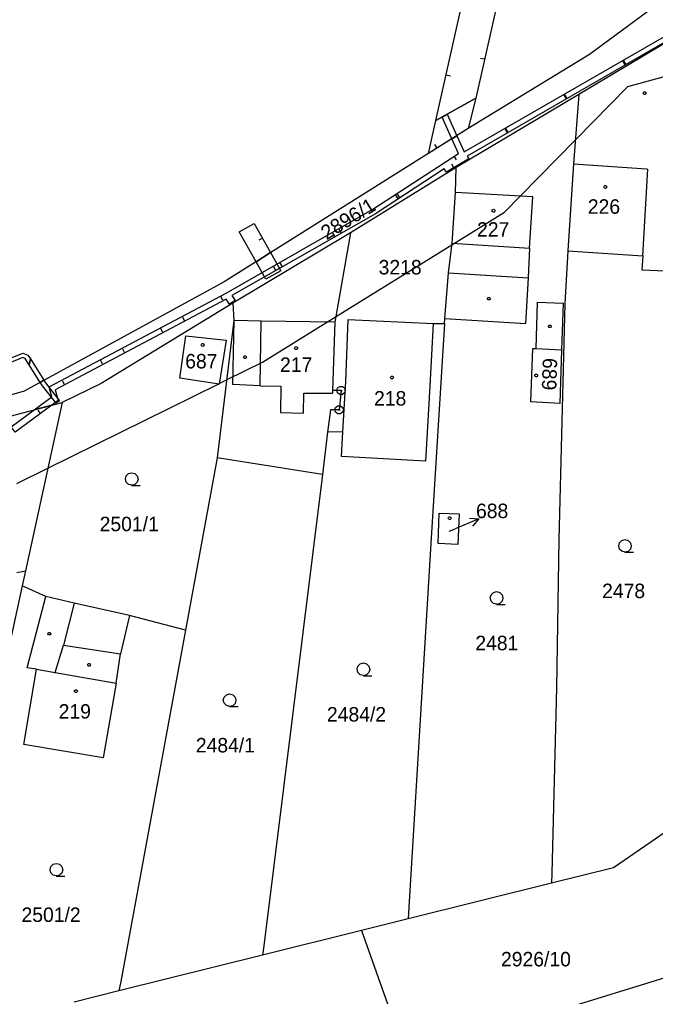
# Model space of a CAD drawing. Extents: x -760611 to -758411, y -1176479 to -1174807.
# Drawn here: x -759231.6 to -759156.8, y -1175131 to -1175016.2 of the extents above; entities that cross this region are included whole.
import ezdxf

# ---------------------------------------------------------------- set-up
doc = ezdxf.new("R2010")
doc.units = 0
for name, color, linetype in [('1', 7, 'Continuous'), ('11', 7, 'Continuous'), ('12', 7, 'Continuous'), ('13', 7, 'Continuous'), ('2', 7, 'Continuous'), ('3', 7, 'Continuous'), ('4', 7, 'Continuous'), ('5', 7, 'Continuous'), ('7', 7, 'Continuous'), ('8', 7, 'Continuous')]:
    doc.layers.add(name, color=color, linetype=linetype)

msp = doc.modelspace()

# ---------------------------------------------------------------- linework, layer by layer
at = {"layer": '1'}
for p, q in [((-759150.3, -1175009.76), (-759164.6, -1175020.29)), ((-759153.04, -1175017.37), (-759165.84, -1175024.98)), ((-759164.6, -1175020.29), (-759178.88, -1175029.01)), ((-759165.84, -1175024.98), (-759180.26, -1175033.56)), ((-759165.84, -1175024.98), (-759166.46, -1175033.14)), ((-759178.88, -1175029.01), (-759207.54, -1175047)), ((-759180.26, -1175033.56), (-759192.72, -1175041.24)), ((-759180.34, -1175036.5), (-759180.26, -1175033.56)), ((-759166.46, -1175033.14), (-759167.14, -1175043.36)), ((-759180.75, -1175042.45), (-759180.34, -1175036.5)), ((-759171.27, -1175037.03), (-759180.34, -1175036.5)), ((-759171.64, -1175043.06), (-759171.27, -1175037.03)), ((-759192.72, -1175041.24), (-759206.53, -1175049.53)), ((-759192.72, -1175041.24), (-759194.56, -1175051.73)), ((-759181.19, -1175045.94), (-759180.75, -1175042.45)), ((-759171.64, -1175043.06), (-759171.82, -1175046.55)), ((-759167.14, -1175043.36), (-759167.51, -1175049.56)), ((-759167.14, -1175043.36), (-759158.34, -1175043.97)), ((-759158.34, -1175043.97), (-759158.43, -1175045.59)), ((-759181.59, -1175051.31), (-759181.19, -1175045.94)), ((-759158.43, -1175045.59), (-759155.64, -1175045.71)), ((-759207.54, -1175047), (-759231.08, -1175059.85)), ((-759171.82, -1175046.55), (-759172.14, -1175051.92)), ((-759206.53, -1175049.53), (-759222.03, -1175058.94)), ((-759206.53, -1175049.53), (-759206.43, -1175051.56)), ((-759170.88, -1175054.86), (-759170.7, -1175049.4)), ((-759170.7, -1175049.4), (-759167.7, -1175049.53)), ((-759167.51, -1175049.56), (-759168.22, -1175077.29)), ((-759167.7, -1175049.53), (-759167.88, -1175055.01)), ((-759206.43, -1175051.56), (-759208.4, -1175067.69)), ((-759194.56, -1175051.73), (-759194.81, -1175059.76)), ((-759193.25, -1175058.7), (-759192.99, -1175051.42)), ((-759192.99, -1175051.42), (-759182.96, -1175051.89)), ((-759182.96, -1175051.89), (-759183.37, -1175059.25)), ((-759181.63, -1175051.91), (-759183.24, -1175077.74)), ((-759182.96, -1175051.89), (-759181.63, -1175051.91)), ((-759181.63, -1175051.91), (-759181.59, -1175051.31)), ((-759181.59, -1175051.31), (-759172.14, -1175051.92)), ((-759212.79, -1175058.33), (-759212.05, -1175053.35)), ((-759212.05, -1175053.35), (-759207.34, -1175053.87)), ((-759207.34, -1175053.87), (-759208.15, -1175059.04)), ((-759171.51, -1175061.09), (-759171.25, -1175054.84)), ((-759171.25, -1175054.84), (-759170.88, -1175054.86)), ((-759167.88, -1175055.01), (-759168.08, -1175061.3)), ((-759222.03, -1175058.94), (-759226.61, -1175061.18)), ((-759208.15, -1175059.04), (-759212.79, -1175058.33)), ((-759193.59, -1175064.62), (-759193.25, -1175058.7)), ((-759231.08, -1175059.85), (-759242.58, -1175063.11)), ((-759193.81, -1175059.77), (-759194.81, -1175059.76)), ((-759193.81, -1175059.77), (-759194.04, -1175062.06)), ((-759183.37, -1175059.25), (-759183.87, -1175068.09)), ((-759259.32, -1175069.76), (-759226.61, -1175061.18)), ((-759226.61, -1175061.18), (-759230.92, -1175080.96)), ((-759168.08, -1175061.3), (-759171.51, -1175061.09)), ((-759195.04, -1175062.03), (-759195.39, -1175064.66)), ((-759194.04, -1175062.06), (-759195.04, -1175062.03)), ((-759195.39, -1175064.66), (-759196.01, -1175069.63)), ((-759193.59, -1175064.62), (-759195.39, -1175064.66)), ((-759193.75, -1175067.53), (-759193.59, -1175064.62)), ((-759208.4, -1175067.69), (-759212.12, -1175087.92)), ((-759196.01, -1175069.63), (-759208.4, -1175067.69)), ((-759183.87, -1175068.09), (-759193.75, -1175067.53)), ((-759196.01, -1175069.63), (-759202.91, -1175125.02)), ((-759182.41, -1175077.77), (-759182.26, -1175074.18)), ((-759182.26, -1175074.18), (-759179.92, -1175074.28)), ((-759179.92, -1175074.28), (-759180.08, -1175077.88)), ((-759168.22, -1175077.29), (-759168.47, -1175094.73)), ((-759183.24, -1175077.74), (-759185.84, -1175120.5)), ((-759180.08, -1175077.88), (-759182.41, -1175077.77)), ((-759231.94, -1175081.17), (-759230.92, -1175080.96)), ((-759230.92, -1175080.96), (-759231.31, -1175082.74)), ((-759231.31, -1175082.74), (-759244.42, -1175142.81)), ((-759228.54, -1175083.99), (-759231.31, -1175082.74)), ((-759230.73, -1175092.35), (-759228.54, -1175083.99)), ((-759225.18, -1175084.75), (-759228.54, -1175083.99)), ((-759218.69, -1175086.22), (-759225.18, -1175084.75)), ((-759218.69, -1175086.22), (-759219.74, -1175090.73)), ((-759212.12, -1175087.92), (-759218.69, -1175086.22)), ((-759212.12, -1175087.92), (-759219.73, -1175129.23)), ((-759220.24, -1175094.16), (-759219.74, -1175090.73)), ((-759231.11, -1175101.38), (-759229.64, -1175092.53)), ((-759229.64, -1175092.53), (-759230.73, -1175092.35)), ((-759220.24, -1175094.16), (-759221.77, -1175102.93)), ((-759168.47, -1175094.73), (-759169.03, -1175116.5)), ((-759221.77, -1175102.93), (-759231.11, -1175101.38)), ((-759154.5, -1175110.85), (-759161.77, -1175115.86)), ((-759161.77, -1175115.86), (-759169.06, -1175117.68)), ((-759169.03, -1175116.5), (-759169.06, -1175117.68)), ((-759169.06, -1175117.68), (-759185.93, -1175121.87)), ((-759185.84, -1175120.5), (-759185.93, -1175121.87)), ((-759185.93, -1175121.87), (-759191.41, -1175123.23)), ((-759191.41, -1175123.23), (-759203.05, -1175126.12)), ((-759191.41, -1175123.23), (-759185.78, -1175139)), ((-759202.91, -1175125.02), (-759203.05, -1175126.12)), ((-759203.05, -1175126.12), (-759219.93, -1175130.32)), ((-759149.08, -1175126.73), (-759169.45, -1175133.02)), ((-759219.73, -1175129.23), (-759219.93, -1175130.32)), ((-759219.93, -1175130.32), (-759225.2, -1175131.63))]:
    msp.add_line(p, q, dxfattribs=at)
at = {"layer": '11'}
for points in [[(-758949.2, -1174976.06), (-758977.51, -1174978.74), (-758983.13, -1174979.27), (-758986.95, -1174979.9), (-758999.15, -1174981.9), (-759005.62, -1174982.97), (-759027.3, -1174991.01), (-759057.42, -1175002.17), (-759065.49, -1175005.94), (-759070.45, -1175006.82), (-759079.49, -1175008.41), (-759092.2, -1175010.11), (-759110.03, -1175012.49), (-759116.16, -1175014.27), (-759121.49, -1175015.82), (-759122.18, -1175015.72), (-759124.46, -1175015.38), (-759134.22, -1175017.02), (-759144.38, -1175019.8), (-759148.15, -1175020.83), (-759150.25, -1175021.4), (-759160.11, -1175024.09)], [(-759231.94, -1175070.7), (-759228.29, -1175068.9), (-759208.26, -1175059.02), (-759208.14, -1175058.96), (-759207.28, -1175058.54), (-759203.05, -1175056.46), (-759194.46, -1175051.13), (-759180.78, -1175042.66), (-759174.58, -1175038.82), (-759172.73, -1175036.94), (-759166.25, -1175030.34), (-759160.11, -1175024.09)]]:
    msp.add_lwpolyline(points, dxfattribs=at)
at = {"layer": '12'}
for p, q in [((-759166.46, -1175033.14), (-759167.14, -1175043.36)), ((-759166.46, -1175033.14), (-759157.9, -1175033.74)), ((-759158.34, -1175043.97), (-759157.74, -1175033.75)), ((-759157.9, -1175033.74), (-759157.74, -1175033.75)), ((-759180.75, -1175042.45), (-759180.34, -1175036.5)), ((-759171.27, -1175037.03), (-759180.34, -1175036.5)), ((-759171.64, -1175043.06), (-759171.27, -1175037.03)), ((-759180.75, -1175042.45), (-759171.64, -1175043.06)), ((-759167.14, -1175043.36), (-759158.34, -1175043.97)), ((-759203.32, -1175059.23), (-759203.22, -1175051.61)), ((-759194.56, -1175051.73), (-759203.22, -1175051.61)), ((-759194.56, -1175051.73), (-759194.81, -1175059.76)), ((-759193.25, -1175058.7), (-759192.99, -1175051.42)), ((-759192.99, -1175051.42), (-759182.96, -1175051.89)), ((-759182.96, -1175051.89), (-759183.37, -1175059.25)), ((-759212.79, -1175058.33), (-759212.05, -1175053.35)), ((-759212.05, -1175053.35), (-759207.34, -1175053.87)), ((-759207.34, -1175053.87), (-759208.15, -1175059.04)), ((-759171.51, -1175061.09), (-759171.25, -1175054.84)), ((-759171.25, -1175054.84), (-759170.88, -1175054.86)), ((-759170.88, -1175054.86), (-759167.88, -1175055.01)), ((-759167.88, -1175055.01), (-759168.08, -1175061.3)), ((-759208.15, -1175059.04), (-759212.79, -1175058.33)), ((-759193.59, -1175064.62), (-759193.25, -1175058.7)), ((-759203.32, -1175059.23), (-759200.9, -1175059.26)), ((-759200.9, -1175059.26), (-759200.95, -1175062.38)), ((-759198.22, -1175062.42), (-759198.19, -1175060.09)), ((-759198.19, -1175060.09), (-759194.82, -1175060.1)), ((-759194.81, -1175059.76), (-759194.82, -1175060.1)), ((-759183.37, -1175059.25), (-759183.87, -1175068.09)), ((-759168.08, -1175061.3), (-759171.51, -1175061.09)), ((-759200.95, -1175062.38), (-759198.22, -1175062.42)), ((-759193.75, -1175067.53), (-759193.59, -1175064.62)), ((-759183.87, -1175068.09), (-759193.75, -1175067.53)), ((-759182.41, -1175077.77), (-759182.26, -1175074.18)), ((-759182.26, -1175074.18), (-759179.92, -1175074.28)), ((-759179.92, -1175074.28), (-759180.08, -1175077.88)), ((-759180.08, -1175077.88), (-759182.41, -1175077.77)), ((-759231.11, -1175101.38), (-759229.64, -1175092.53)), ((-759229.64, -1175092.53), (-759227.42, -1175092.9)), ((-759227.42, -1175092.9), (-759220.24, -1175094.16)), ((-759220.24, -1175094.16), (-759221.77, -1175102.93)), ((-759221.77, -1175102.93), (-759231.11, -1175101.38))]:
    msp.add_line(p, q, dxfattribs=at)
at = {"layer": '13'}
for p, q in [((-759176.94, -1175020.86), (-759177.43, -1175020.75)), ((-759160.71, -1175021.02), (-759160.46, -1175021.45)), ((-759160.3, -1175021.47), (-759160.55, -1175021.03)), ((-759181.45, -1175022.7), (-759180.96, -1175022.81)), ((-759177.96, -1175025.41), (-759182.65, -1175028.07)), ((-759182.65, -1175028.07), (-759177.96, -1175025.41)), ((-759167.64, -1175025.01), (-759167.39, -1175025.44)), ((-759167.23, -1175025.46), (-759167.48, -1175025.03)), ((-759181.93, -1175027.66), (-759181.33, -1175027.32)), ((-759180.78, -1175030.2), (-759181.93, -1175027.66)), ((-759181.33, -1175027.32), (-759180.2, -1175029.84)), ((-759174.57, -1175029), (-759174.32, -1175029.43)), ((-759174.16, -1175029.45), (-759174.41, -1175029.02)), ((-759180.2, -1175029.84), (-759180.78, -1175030.2)), ((-759182.51, -1175031.29), (-759182.78, -1175030.86)), ((-759180.55, -1175032.26), (-759180.27, -1175032.68)), ((-759180.54, -1175033.61), (-759180.79, -1175033.18)), ((-759187.1, -1175037.26), (-759187.37, -1175036.84)), ((-759187.25, -1175036.63), (-759186.97, -1175037.05)), ((-759194.54, -1175041.73), (-759194.79, -1175041.29)), ((-759194.09, -1175040.77), (-759193.84, -1175041.2)), ((-759203.06, -1175041.87), (-759203.49, -1175042.11)), ((-759203.8, -1175044.65), (-759202.09, -1175043.58)), ((-759202.09, -1175043.58), (-759200.88, -1175045.71)), ((-759202.64, -1175046.7), (-759203.8, -1175044.65)), ((-759201.04, -1175044.74), (-759200.79, -1175045.17)), ((-759200.88, -1175045.71), (-759202.64, -1175046.7)), ((-759201.49, -1175045.69), (-759201.73, -1175045.26)), ((-759207.99, -1175048.68), (-759207.76, -1175049.12)), ((-759212.17, -1175051.63), (-759212.41, -1175051.19)), ((-759215.06, -1175052.43), (-759214.83, -1175052.87)), ((-759219.25, -1175055.37), (-759219.48, -1175054.92)), ((-759230.48, -1175056.77), (-759230.35, -1175056.06)), ((-759230.35, -1175056.06), (-759228.75, -1175058.58)), ((-759222.13, -1175056.17), (-759221.9, -1175056.61)), ((-759229.19, -1175058.82), (-759230.48, -1175056.77)), ((-759229.19, -1175058.82), (-759228.75, -1175058.58)), ((-759228.75, -1175058.58), (-759229.19, -1175058.82)), ((-759228.94, -1175059.21), (-759229.19, -1175058.82)), ((-759228.75, -1175058.58), (-759228.56, -1175058.87)), ((-759228.56, -1175058.87), (-759226.92, -1175060.98)), ((-759226.32, -1175059.1), (-759226.55, -1175058.66)), ((-759227.32, -1175061.28), (-759228.94, -1175059.21)), ((-759226.92, -1175060.98), (-759227.32, -1175061.28)), ((-759229.15, -1175062.48), (-759229.45, -1175062.08))]:
    msp.add_line(p, q, dxfattribs=at)
for points in [[(-759182.65, -1175028.07), (-759174.59, -1174992.11), (-759172.64, -1174983.41)], [(-759168.73, -1174984.27), (-759170.69, -1174992.98), (-759174.4, -1175009.55), (-759177.96, -1175025.41)], [(-759179.34, -1175031.74), (-759155.5, -1175018.02), (-759150.23, -1175014.64), (-759151.48, -1175010.63), (-759150.8, -1175010.13), (-759149.44, -1175014.48), (-759138.98, -1175005.71), (-759124.75, -1174987.85), (-759120.27, -1174989.2)], [(-759155.53, -1175018.72), (-759178.98, -1175032.23), (-759178.78, -1175032.57), (-759181.42, -1175034.14), (-759181.67, -1175033.72), (-759189.76, -1175039)], [(-759177.96, -1175025.41), (-759178.88, -1175029.01), (-759183.52, -1175031.92), (-759182.65, -1175028.07)], [(-759227.82, -1175060.51), (-759228.14, -1175059.35), (-759207.33, -1175048.33), (-759190.08, -1175038.48), (-759180.01, -1175031.91), (-759180.78, -1175030.2), (-759180.2, -1175029.84), (-759179.34, -1175031.74)], [(-759189.76, -1175039), (-759206.64, -1175048.63), (-759206.26, -1175049.22), (-759206.93, -1175049.63), (-759207.31, -1175049.06)], [(-759207.31, -1175049.06), (-759227.43, -1175059.69), (-759227.07, -1175060.95), (-759227.81, -1175061.49), (-759229.9, -1175062.04), (-759227.82, -1175060.51)]]:
    msp.add_lwpolyline(points, dxfattribs=at)
for points in [[(-759203.8, -1175044.65), (-759205.78, -1175041.15), (-759204.02, -1175040.16), (-759202.09, -1175043.58)], [(-759280.32, -1175069.22), (-759280.19, -1175068.65), (-759275.46, -1175067.4), (-759267.57, -1175065.52), (-759257.68, -1175064.32), (-759246.5, -1175060.39), (-759241.38, -1175059.01), (-759235.85, -1175057.24), (-759231.22, -1175055.37), (-759230.63, -1175055.61), (-759230.35, -1175056.06), (-759230.48, -1175056.77), (-759230.97, -1175056.01), (-759231.23, -1175055.9), (-759235.83, -1175057.76), (-759241.1, -1175059.45), (-759246.41, -1175060.91), (-759257.6, -1175064.67), (-759257.79, -1175064.7), (-759260.43, -1175065.05), (-759266.85, -1175065.91), (-759275.26, -1175067.9)], [(-759232.14, -1175064.69), (-759232.61, -1175064.04), (-759229.9, -1175062.04), (-759227.81, -1175061.49)]]:
    msp.add_lwpolyline(points, close=True, dxfattribs=at)
at = {"layer": '3'}
for points in [[(-759218.42, -1175070.91), (-759218.8, -1175070.81), (-759219.07, -1175070.54), (-759219.17, -1175070.17), (-759219.07, -1175069.8), (-759218.8, -1175069.53), (-759218.43, -1175069.43), (-759218.06, -1175069.53), (-759217.79, -1175069.8), (-759217.69, -1175070.18), (-759217.79, -1175070.56), (-759218.06, -1175070.83), (-759218.44, -1175070.93), (-759217.44, -1175070.93)], [(-759160.41, -1175078.77), (-759160.79, -1175078.67), (-759161.06, -1175078.4), (-759161.16, -1175078.03), (-759161.06, -1175077.66), (-759160.79, -1175077.39), (-759160.42, -1175077.29), (-759160.05, -1175077.39), (-759159.78, -1175077.66), (-759159.68, -1175078.04), (-759159.78, -1175078.42), (-759160.05, -1175078.69), (-759160.43, -1175078.79), (-759159.43, -1175078.79)], [(-759175.51, -1175084.89), (-759175.89, -1175084.79), (-759176.16, -1175084.52), (-759176.26, -1175084.15), (-759176.16, -1175083.78), (-759175.89, -1175083.51), (-759175.52, -1175083.41), (-759175.15, -1175083.51), (-759174.88, -1175083.78), (-759174.78, -1175084.16), (-759174.88, -1175084.54), (-759175.15, -1175084.81), (-759175.53, -1175084.91), (-759174.53, -1175084.91)], [(-759191.17, -1175093.27), (-759191.55, -1175093.17), (-759191.82, -1175092.9), (-759191.92, -1175092.53), (-759191.82, -1175092.16), (-759191.55, -1175091.89), (-759191.18, -1175091.79), (-759190.81, -1175091.89), (-759190.54, -1175092.16), (-759190.44, -1175092.54), (-759190.54, -1175092.92), (-759190.81, -1175093.19), (-759191.19, -1175093.29), (-759190.19, -1175093.29)], [(-759206.91, -1175096.9), (-759207.29, -1175096.8), (-759207.56, -1175096.53), (-759207.66, -1175096.16), (-759207.56, -1175095.79), (-759207.29, -1175095.52), (-759206.92, -1175095.42), (-759206.55, -1175095.52), (-759206.28, -1175095.79), (-759206.18, -1175096.17), (-759206.28, -1175096.55), (-759206.55, -1175096.82), (-759206.93, -1175096.92), (-759205.93, -1175096.92)], [(-759227.28, -1175116.82), (-759227.66, -1175116.72), (-759227.93, -1175116.45), (-759228.03, -1175116.08), (-759227.93, -1175115.71), (-759227.66, -1175115.44), (-759227.29, -1175115.34), (-759226.92, -1175115.44), (-759226.65, -1175115.71), (-759226.55, -1175116.09), (-759226.65, -1175116.47), (-759226.92, -1175116.74), (-759227.3, -1175116.84), (-759226.3, -1175116.84)]]:
    msp.add_lwpolyline(points, dxfattribs=at)
at = {"layer": '4'}
for p, q in [((-759166.46, -1175033.14), (-759157.9, -1175033.74)), ((-759158.34, -1175043.97), (-759157.74, -1175033.75)), ((-759157.9, -1175033.74), (-759157.74, -1175033.75)), ((-759180.75, -1175042.45), (-759171.64, -1175043.06)), ((-759181.19, -1175045.94), (-759171.82, -1175046.55)), ((-759206.43, -1175051.56), (-759206.59, -1175059.07)), ((-759203.22, -1175051.61), (-759206.43, -1175051.56)), ((-759203.32, -1175059.23), (-759203.22, -1175051.61)), ((-759194.56, -1175051.73), (-759203.22, -1175051.61)), ((-759170.88, -1175054.86), (-759167.88, -1175055.01)), ((-759203.32, -1175059.23), (-759206.59, -1175059.07)), ((-759203.32, -1175059.23), (-759200.9, -1175059.26)), ((-759200.9, -1175059.26), (-759200.95, -1175062.38)), ((-759198.22, -1175062.42), (-759198.19, -1175060.09)), ((-759198.19, -1175060.09), (-759194.82, -1175060.1)), ((-759194.81, -1175059.76), (-759194.82, -1175060.1)), ((-759200.95, -1175062.38), (-759198.22, -1175062.42)), ((-759225.18, -1175084.75), (-759226.44, -1175089.71)), ((-759227.42, -1175092.9), (-759226.44, -1175089.71)), ((-759226.44, -1175089.71), (-759219.74, -1175090.73)), ((-759229.64, -1175092.53), (-759227.42, -1175092.9)), ((-759227.42, -1175092.9), (-759220.24, -1175094.16))]:
    msp.add_line(p, q, dxfattribs=at)
at = {"layer": '5'}
for points in [[(-759158.03, -1175024.7), (-759157.94, -1175024.85), (-759158.03, -1175025), (-759158.21, -1175025), (-759158.3, -1175024.85), (-759158.21, -1175024.7)], [(-759162.73, -1175035.69), (-759162.63, -1175035.71), (-759162.58, -1175035.8), (-759162.56, -1175035.86), (-759162.58, -1175035.95), (-759162.66, -1175036.02), (-759162.73, -1175036.03), (-759162.82, -1175036), (-759162.88, -1175035.94), (-759162.9, -1175035.86), (-759162.88, -1175035.77), (-759162.8, -1175035.7)], [(-759175.89, -1175038.48), (-759175.79, -1175038.5), (-759175.74, -1175038.59), (-759175.72, -1175038.65), (-759175.74, -1175038.74), (-759175.82, -1175038.81), (-759175.89, -1175038.82), (-759175.98, -1175038.79), (-759176.04, -1175038.73), (-759176.06, -1175038.65), (-759176.04, -1175038.56), (-759175.96, -1175038.49)], [(-759176.34, -1175048.83), (-759176.25, -1175048.98), (-759176.34, -1175049.13), (-759176.52, -1175049.13), (-759176.61, -1175048.98), (-759176.52, -1175048.83)], [(-759169.17, -1175052.08), (-759169.08, -1175052.23), (-759169.17, -1175052.38), (-759169.35, -1175052.38), (-759169.44, -1175052.23), (-759169.35, -1175052.08)], [(-759210.08, -1175054.25), (-759209.98, -1175054.27), (-759209.93, -1175054.36), (-759209.91, -1175054.42), (-759209.93, -1175054.51), (-759210.01, -1175054.58), (-759210.08, -1175054.59), (-759210.17, -1175054.56), (-759210.23, -1175054.5), (-759210.25, -1175054.42), (-759210.23, -1175054.33), (-759210.15, -1175054.26)], [(-759199.1, -1175054.63), (-759199, -1175054.65), (-759198.95, -1175054.74), (-759198.93, -1175054.8), (-759198.95, -1175054.89), (-759199.03, -1175054.96), (-759199.1, -1175054.97), (-759199.19, -1175054.94), (-759199.25, -1175054.88), (-759199.27, -1175054.8), (-759199.25, -1175054.71), (-759199.17, -1175054.64)], [(-759205.01, -1175055.71), (-759204.92, -1175055.86), (-759205.01, -1175056.01), (-759205.19, -1175056.01), (-759205.28, -1175055.86), (-759205.19, -1175055.71)], [(-759187.82, -1175058.08), (-759187.72, -1175058.1), (-759187.67, -1175058.19), (-759187.65, -1175058.25), (-759187.67, -1175058.34), (-759187.75, -1175058.41), (-759187.82, -1175058.42), (-759187.91, -1175058.39), (-759187.97, -1175058.33), (-759187.99, -1175058.25), (-759187.97, -1175058.16), (-759187.89, -1175058.09)], [(-759170.87, -1175057.84), (-759170.77, -1175057.86), (-759170.72, -1175057.95), (-759170.7, -1175058.01), (-759170.72, -1175058.1), (-759170.8, -1175058.17), (-759170.87, -1175058.18), (-759170.96, -1175058.15), (-759171.02, -1175058.09), (-759171.04, -1175058.01), (-759171.02, -1175057.92), (-759170.94, -1175057.85)], [(-759181.04, -1175074.6), (-759180.94, -1175074.62), (-759180.89, -1175074.71), (-759180.87, -1175074.77), (-759180.89, -1175074.86), (-759180.97, -1175074.93), (-759181.04, -1175074.94), (-759181.13, -1175074.91), (-759181.19, -1175074.85), (-759181.21, -1175074.77), (-759181.19, -1175074.68), (-759181.11, -1175074.61)], [(-759228.02, -1175088.2), (-759227.93, -1175088.35), (-759228.02, -1175088.5), (-759228.2, -1175088.5), (-759228.29, -1175088.35), (-759228.2, -1175088.2)], [(-759223.38, -1175091.87), (-759223.29, -1175092.02), (-759223.38, -1175092.17), (-759223.56, -1175092.17), (-759223.65, -1175092.02), (-759223.56, -1175091.87)], [(-759224.99, -1175094.93), (-759224.89, -1175094.95), (-759224.84, -1175095.04), (-759224.82, -1175095.1), (-759224.84, -1175095.19), (-759224.92, -1175095.26), (-759224.99, -1175095.27), (-759225.08, -1175095.24), (-759225.14, -1175095.18), (-759225.16, -1175095.1), (-759225.14, -1175095.01), (-759225.06, -1175094.94)]]:
    msp.add_lwpolyline(points, close=True, dxfattribs=at)
at = {"layer": '7'}
for p in [(-759177.6, -1175074.87), (-759181.09, -1175076.3)]:
    msp.add_line(p, (-759180.38, -1175076.01), dxfattribs=at)
msp.add_lwpolyline([(-759178.72, -1175074.79), (-759177.6, -1175074.87), (-759178.34, -1175075.71)], dxfattribs=at)
at = {"layer": '8'}
for p, q in [((-759193.93, -1175059.77), (-759193.69, -1175059.77)), ((-759194.16, -1175062.06), (-759193.92, -1175062.06))]:
    msp.add_line(p, q, dxfattribs=at)
for points in [[(-759193.66, -1175059.29), (-759193.41, -1175059.47), (-759193.31, -1175059.76), (-759193.41, -1175060.05), (-759193.66, -1175060.23), (-759193.97, -1175060.23), (-759194.22, -1175060.05), (-759194.32, -1175059.76), (-759194.22, -1175059.47), (-759193.97, -1175059.29)], [(-759193.89, -1175061.58), (-759193.64, -1175061.76), (-759193.54, -1175062.05), (-759193.64, -1175062.34), (-759193.89, -1175062.52), (-759194.2, -1175062.52), (-759194.45, -1175062.34), (-759194.55, -1175062.05), (-759194.45, -1175061.76), (-759194.2, -1175061.58)]]:
    msp.add_lwpolyline(points, close=True, dxfattribs=at)

# ---------------------------------------------------------------- texts
at = {"layer": '2'}
for s, rotation, p in [('2896/1', 31.4554, (-759195.51, -1175042.14)), ('689', 268.087, (-759170.08, -1175055.93))]:
    msp.add_text(s, height=1.7, rotation=rotation, dxfattribs=at).set_placement(p)
for s, height, p in [('226', 1.7, (-759164.79, -1175039.01)), ('227', 1.7, (-759177.82, -1175041.7)), ('3218', 1.7, (-759189.39, -1175046.14)), ('687', 1.7, (-759212.14, -1175057.18)), ('217', 1.7, (-759200.99, -1175057.59)), ('218', 1.7, (-759189.93, -1175061.55)), ('2501/1', 1.7, (-759222.2, -1175076.31)), ('688', 0.1, (-759181.21, -1175076.3)), ('2478', 1.7, (-759163.11, -1175084.17)), ('2481', 1.7, (-759178.02, -1175090.29)), ('219', 1.7, (-759227.02, -1175098.33)), ('2484/2', 1.7, (-759195.47, -1175098.67)), ('2484/1', 1.7, (-759210.89, -1175102.3)), ('2501/2', 1.7, (-759231.39, -1175122.22)), ('2926/10', 1.7, (-759175, -1175127.44))]:
    msp.add_text(s, height=height, dxfattribs=at).set_placement(p)
at = {"layer": '7'}
msp.add_text('688', height=1.7, dxfattribs=at).set_placement((-759177.94, -1175074.77))

doc.saveas('drawing.dxf')
